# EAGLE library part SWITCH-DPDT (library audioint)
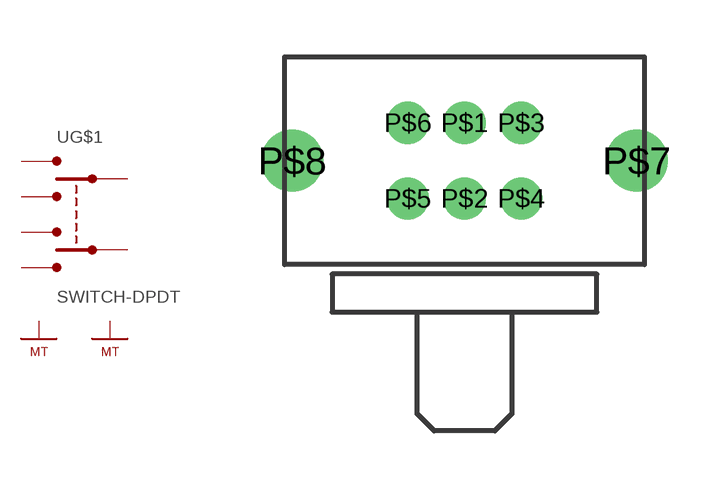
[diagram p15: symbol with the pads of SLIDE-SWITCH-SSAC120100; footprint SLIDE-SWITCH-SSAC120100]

Designator prefix -; gates G$1=SWITCH-DPDT G$2=MECHANICAL G$3=MECHANICAL

## SWITCH-DPDT  [SLIDE-SWITCH-SSAC120100]
P$1  G$1:P$5
P$2  G$1:P$6
P$3  G$1:P$2
P$4  G$1:P$4
P$5  G$1:P$3
P$6  G$1:P$1
P$7  G$2:MT  pas
P$8  G$3:MT  pas

## Footprint SLIDE-SWITCH-SSAC120100 (pad centres in mm)
drill 0.61 round: P$1 0,1; P$2 0,-1; P$3 1.5,1; P$4 1.5,-1; P$5 -1.5,-1; P$6 -1.5,1
drill 1.092 round: P$7 4.55,0; P$8 -4.55,0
